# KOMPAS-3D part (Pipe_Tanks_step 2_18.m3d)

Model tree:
1. X Axis
2. Y Axis
3. Z Axis  (labels: Valve Dy 50; Pipe Dn 50)
     Òîëùèíà ñòåíêè 1 = 1

Referenced files in C:\Documents and Settings\kashirsky\Мои документы\Camtasia Studio\Pipelines3D\Tanks\: Tanks_step 2.a3d
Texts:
  Pipe Dn 50
  Steel ASTM A295
  Three Point Plane
  Plane at Angle
  Line and Point Plane
  Axis through Two Vertices
  Axis of Feature
  Axis of Conical Surface
  Axis through Edge
  Trim by Surface
  Trim by Sketch
  Feature with No History
  Intersection Axis of Two Planes
  Two Line Plane
  Line and Face Plane
  Bend by line
  Hole in sheet body
  Cut in sheet body
  Point in CM
  Linear Dimension from Line to Point
  Surface Finish Symbol
  Geometric Tolerance Symbol
  Leader #1
  Leader #2
  Leader #3
  Shape Deviations and Datum
  Node point number
  Mark of coordination axis
  Node point designation
  Mark/Reference designation with leader
  Mark/reference designation on line
  Mark/Reference designation without leader
  Valve Dy 50
  Plane of section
